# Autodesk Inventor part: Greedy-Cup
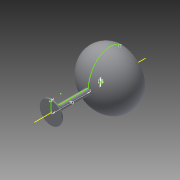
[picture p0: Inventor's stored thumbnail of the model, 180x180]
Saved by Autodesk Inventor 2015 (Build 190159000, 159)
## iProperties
Created: 2017-03
Part Number: Greedy-Cup
Material: Generisch
Document SubType Name: Modeling
Designer: Andreas
Density: 1 g/cm^3
Appearance: Vorgabe
Author: Andreas
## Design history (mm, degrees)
sketch "Skizze1"
  geometry: L1 (-34.783, 5)-(0, 5); L2 (-39.799, 5)-(-89.626, 5); L3 (-34.783, 5)-(35.217, 5); L4 (-33.283, 0)-(-33.283, 0); L5 (-34.783, 3.5)-(0, 3.5); L6 (-34.783, 2)-(0, 2); L7 (-34.783, 1)-(0, 1); L8 (0, 2)-(0, 1); L9 (-136.265, 0)-(63.797, 0) reference; L10 (-34.783, 1)-(-104.783, 1); L11 (-34.783, 1)-(35.217, 1); L12 (-34.783, 3.5)-(-34.783, 2); L13 (-104.783, 20)-(-106.783, 20); L14 (-106.783, 20)-(-106.783, 1); L15 (-106.783, 1)-(-104.783, 1); L16 (5, 0)-(3.5, 0); A1 r 3 centre (17.185, 42.265) between (17.096, 39.266) and (20, 43.301); A2 r 5 centre (0, 0) between (5, 0) and (0, 5); A3 r 3.5 centre (0, 0) between (3.5, 0) and (0, 3.5); A4 r 15.843 centre (-88.962, 20.829) between (-104.783, 20) and (-89.626, 5); 1 further point; 2 other entities
  constraints: 30 end point, 8 point on circle, 5 horizontal, 4 centre point, 3 perpendicular, 2 collinear, 1 coincident, 9 other
  dimensions: "d2" = 3 radius of A1; "d12" = 1.5 distance between parallel lines of L1 L5; "d13" = 1.5 distance between parallel lines of L5 L6; "d14" = 1 distance between parallel lines of L6 L7; "d15" = 70 distance of L7.start L10.end; "d18" = 2 distance of L13.start L13.end
revolve "Umdrehung1" sketch "Skizze1" stored, may be unused: angle "d19" = 90 deg
workplane "Arbeitsebene1"
sketch "Skizze2"
  geometry: L1 (0, 0)-(0, 51.879) reference; L2 (39.266, 51.879)-(-39.266, 51.879) reference; L3 (5, 0)-(-5, 0) reference; L4 (3.5, 34.783)-(-3.5, 34.783) reference; 2 further points
  node "Projizierte Kontur1"
workplane "Arbeitsebene3"
hole "Bohrung2" sketch "Skizze2" diameter "d29" = 3; stored, may be unused: countersink angle "d33" = 90 deg, drill point angle "d35" = 118 deg; dims "d30" = 6, "d31" = 4, "d32" = 2, "d34" = 8
node "Volumenkörper1"
other parameters: "d28" = -2
